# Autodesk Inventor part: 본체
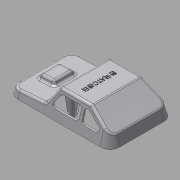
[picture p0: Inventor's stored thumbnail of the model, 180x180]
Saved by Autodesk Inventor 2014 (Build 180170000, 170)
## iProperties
Created: 2007-09
Part Number: 본체
Material: ABS 플라스틱
Document SubType Name: Modeling
Designer: Administrator
Density: 1.06 g/cm^3
Appearance: 매끄러움 - 흰색
Mass: 32.0135 g
Surface Area: 311.497 cm^2
Volume: 30.2014 cm^3
Author: Administrator
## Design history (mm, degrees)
sketch "스케치1"
  geometry: L1 (49, 38)-(-49, 38); L2 (-61, 26)-(-61, -26); L3 (-49, -38)-(49, -38); L4 (61, -26)-(61, 26); L5 (61, 38)-(-61, -38); L6 (-61, 38)-(61, -38); A1 r 12 centre (-49, 26) between (-49, 38) and (-61, 26); A2 r 12 centre (49, 26) between (61, 26) and (49, 38); A3 r 12 centre (49, -26) between (49, -38) and (61, -26); A4 r 12 centre (-49, -26) between (-61, -26) and (-49, -38); 1 further point
  constraints: 12 end point, 8 point on circle, 8 point on line, 8 tangent, 4 centre point, 3 equal radius, 2 midpoint, 2 parallel, 1 horizontal, 1 perpendicular
  dimensions: "d0" = 122 distance of L6.end L5.end; "d1" = 76 distance of L5.end L6.start; "d2" = 12 radius of A1
extrude "돌출1" new body sketch "스케치1" distance "d3" = 30; taper "d4" = -15 deg
sketch "스케치2"
  geometry: L1 (49, 30)-(-49, 30) reference; L2 (-49, 0)-(-61, 0) reference; L3 (-31, 30)-(-61, 30); L4 (-61, 30)-(-61, 10); L5 (-61, 10)-(-31, 30); 1 further point
  constraints: 6 end point, 1 collinear, 1 parallel, 1 perpendicular, 1 vertical alignment
  dimensions: "d6" = 20 distance of L3.end L4.end; "d7" = 30 distance of L3.start L3.end
extrude "돌출2" cut sketch "스케치2" stored distance "d8" = 10; taper "d9" = 0 deg
sketch "스케치3"
  geometry: L1 (61, 30)-(6.628, 30); L2 (6.628, 30)-(19, 10.201); L3 (19, 10.201)-(61, 8); L4 (61, 8)-(61, 30); L5 (49, 30)-(-31, 30) reference; L6 (61, 0)-(49, 0) reference; L7 (-49, 0)-(49, 0) reference; 1 further point
  constraints: 8 end point, 1 collinear, 1 horizontal, 1 perpendicular, 1 vertical alignment
  dimensions: "d10" = 8 distance of L6.start L3.end; "d11" = 3 deg angle of L7 L3; "d12" = 125 deg angle of L3 L2; "d13" = 42 horizontal distance of L2.end L6.start
extrude "돌출3" cut sketch "스케치3" stored distance "d14" = 10; taper "d15" = 0 deg
sketch "스케치4"
  geometry: L1 (-39.881, 9.267)-(-39.881, 61.267) reference; L2 (-31.476, 48.267)-(-11.476, 48.267); L3 (-11.476, 48.267)-(-11.476, 22.267); L4 (-11.476, 22.267)-(-31.476, 22.267); L5 (-31.476, 22.267)-(-31.476, 48.267); L6 (-42.476, 61.267)-(-42.476, 9.267) reference; 3 further points
  constraints: 8 end point, 2 midpoint, 2 parallel, 1 horizontal, 1 horizontal alignment, 1 perpendicular
  dimensions: "d16" = 20 distance between parallel lines of L5 L3; "d17" = 26 distance between parallel lines of L4 L2; "d82" = 11 distance between parallel lines of L5 L6
extrude "돌출4" join sketch "스케치4" distance "d19" = 5; taper "d20" = -20 deg
fillet "모깎기1" dims "d21" = 3
fillet "모깎기2" dims "d22" = 3
fillet "모깎기3" dims "d23" = 3
fillet "모깎기4" dims "d24" = 3
fillet "모깎기5" dims "d25" = 3
feature "쉘1" dims "d26" = 2
sketch "스케치7"
  geometry: L1 (18.172, 11.526)-(7.51, 28.59) reference; L2 (4.965, 30)-(-30.092, 30) reference; L3 (-31.756, 29.496)-(-50.664, 16.891) reference; L4 (10.362, 14.59)-(4.738, 23.59); L5 (2.194, 25)-(-17.77, 25); L6 (7.818, 10)-(-17.77, 10); L7 (-20.77, 13)-(-20.77, 22); L8 (-30.242, 24.496)-(-43.742, 15.496); L9 (-42.078, 10)-(-26.986, 10); L10 (-23.986, 13)-(-23.986, 22); L11 (-26.986, 25)-(-28.578, 25); A1 r 3 centre (-17.77, 13) between (-20.77, 13) and (-17.77, 10); A2 r 3 centre (-17.77, 22) between (-17.77, 25) and (-20.77, 22); A3 r 3 centre (2.194, 22) between (4.738, 23.59) and (2.194, 25); A4 r 3 centre (7.818, 13) between (7.818, 10) and (10.362, 14.59); A5 r 3 centre (-42.078, 13) between (-43.742, 15.496) and (-42.078, 10); A6 r 3 centre (-26.986, 13) between (-26.986, 10) and (-23.986, 13); A7 r 3 centre (-26.986, 22) between (-23.986, 22) and (-26.986, 25); A8 r 3 centre (-28.578, 22) between (-28.578, 25) and (-30.242, 24.496); 7 further points
  constraints: 16 end point, 16 point on circle, 16 tangent, 12 point on line, 8 centre point, 6 equal radius, 5 parallel, 3 perpendicular
  dimensions: "d27" = 5 distance between parallel lines of L2 L5; "d28" = 5 distance between parallel lines of L1 L4; "d29" = 34 distance of point (13.23, 10) point (-20.77, 10); "d30" = 15 distance of point (-20.77, 10) point (-20.77, 25); "d31" = 3 radius of A1; "d32" = 5 distance between parallel lines of L3 L8; "d33" = 5 distance between parallel lines of L2 L11; "d34" = 28 distance of point (-51.986, 10) point (-23.986, 10); "d35" = 15 distance of point (-23.986, 10) point (-23.986, 25); "d36" = 3 radius of A5
extrude "돌출5" cut sketch "스케치7" stored distance "d37" = 5; taper "d38" = 0 deg
sketch "스케치8"
  geometry: L1 (-49, 35.929)-(49, 35.929) reference; L2 (58.929, 26)-(58.929, -26) reference; L3 (49, -35.929)-(-49, -35.929) reference; L4 (-58.929, -26)-(-58.929, 26) reference; L5 (49, 36.929)-(-49, 36.929); L6 (-59.929, 26)-(-59.929, -26); L7 (-49, -36.929)-(49, -36.929); L8 (59.929, -26)-(59.929, 26); A1 r 9.929 centre (49, 26) between (58.929, 26) and (49, 35.929) reference; A2 r 9.929 centre (49, -26) between (49, -35.929) and (58.929, -26) reference; A3 r 9.929 centre (-49, -26) between (-58.929, -26) and (-49, -35.929) reference; A4 r 9.929 centre (-49, 26) between (-49, 35.929) and (-58.929, 26) reference; A5 r 10.929 centre (-49, 26) between (-49, 36.929) and (-59.929, 26); A6 r 10.929 centre (-49, -26) between (-59.929, -26) and (-49, -36.929); A7 r 10.929 centre (49, -26) between (49, -36.929) and (59.929, -26); A8 r 10.929 centre (49, 26) between (59.929, 26) and (49, 36.929); 1 further point
  constraints: 8 end point, 8 point on circle, 4 centre point, 7 other
  dimensions: "d39" = 1 distance between parallel lines of L5 L1
extrude "돌출6" join sketch "스케치8" distance "d40" = 1; taper "d41" = 0 deg
node "작업 평면1"
sketch "스케치9"
  geometry: A1 r 4 centre (21, 0) between (25, 0) and (17, 0); A2 r 4 centre (10, 0) between (14, 0) and (6, 0); A3 r 4 centre (-10, 0) between (-6, 0) and (-14, 0); A4 r 4 centre (-21, 0) between (-17, 0) and (-25, 0); 3 further points
  constraints: 8 point on circle, 4 centre point, 13 other
  dimensions: "d43" = 8 diameter of A1; "d44" = 8 diameter of A2; "d45" = 8 diameter of A3; "d46" = 8 diameter of A4; "d47" = 20 distance of A3.centre A2.centre; "d48" = 10 distance of point (0, 0) A2.centre; "d49" = 11 distance of A1.centre A2.centre; "d50" = 11 distance of A4.centre A3.centre
extrude "돌출7" join sketch "스케치9" stored distance "d51" = 1; taper "d52" = 0 deg
sketch "스케치13"
  geometry: C1 r 3 at (-40, 0); C2 r 3 at (40, 0); C3 r 3 at (0, -22); C4 r 3 at (0, 22); 1 further point
  constraints: 4 centre point, 2 horizontal alignment, 2 vertical alignment
  dimensions: "d83" = 6 diameter of C1; "d84" = 6 diameter of C2; "d85" = 6 diameter of C3; "d86" = 6 diameter of C4; "d87" = 44 distance of C3.centre C4.centre; "d88" = 22 distance of C3.centre point (0, 0); "d89" = 40 distance of C1.centre point (0, 0); "d90" = 40 distance of C2.centre point (0, 0)
extrude "돌출10" join sketch "스케치13" stored distance "d91" = 1; taper "d92" = 2 deg
node "작업 평면3"
sketch "스케치14"
  geometry: L1 (-45, 1)-(-35, 1); L2 (-35, 1)-(-35, -1); L3 (-35, -1)-(-45, -1); L4 (-45, -1)-(-45, 1); L5 (-45, 1)-(-35, -1); L6 (-35, 1)-(-45, -1); L7 (5, 23)-(-5, 23); L8 (-5, 23)-(-5, 21); L9 (-5, 21)-(5, 21); L10 (5, 21)-(5, 23); L11 (5, 23)-(-5, 21); L12 (-5, 23)-(5, 21); L13 (35, 1)-(45, 1); L14 (45, 1)-(45, -1); L15 (45, -1)-(35, -1); L16 (35, -1)-(35, 1); L17 (35, 1)-(45, -1); L18 (45, 1)-(35, -1); L19 (5, -21)-(-5, -21); L20 (-5, -21)-(-5, -23); L21 (-5, -23)-(5, -23); L22 (5, -23)-(5, -21); L23 (5, -21)-(-5, -23); L24 (-5, -21)-(5, -23); C1 r 3 at (0, -22) reference; C2 r 3 at (0, 22) reference; C3 r 3 at (40, 0) reference; C4 r 3 at (-40, 0) reference; 1 further point
  constraints: 48 end point, 8 midpoint, 8 parallel, 4 horizontal, 4 perpendicular
  dimensions: "d94" = 10 distance of L2.end L3.end; "d95" = 2 distance of L1.end L2.end; "d96" = 10 distance of L9.end L8.end; "d97" = 2 distance of L8.end L7.end; "d98" = 10 distance of L14.end L15.end; "d99" = 2 distance of L13.end L14.end; "d100" = 10 distance of L21.end L20.end; "d101" = 2 distance of L20.end L19.end
extrude "돌출11" join sketch "스케치14" stored distance "d102" = 1; taper "d103" = 0.5 deg
sketch "스케치15"
  geometry: L1 (2.098, 0)-(2.324, -26.001) reference; L2 (2.098, 0)-(6.682, -26.001); L3 (27.189, -27.941)-(-7.868, -27.941) reference; L4 (2.324, -26.001)-(6.682, -26.001); 1 further point
  constraints: 4 end point, 1 parallel
  dimensions: "d104" = 80 deg angle of L3 L2
extrude "돌출12" join sketch "스케치15" stored distance "d105" = 1; taper "d106" = 0 deg
sketch "스케치16"
  geometry: L1 (0, 0)-(-3.68, -20.872); L2 (35.092, -27.941)-(0.035, -27.941) reference; L3 (-0.813, -25.471)-(-11.476, -8.367) reference; L4 (-3.68, -20.872)-(0.035, -27.941); L5 (0.035, -27.941)-(0, 0); 1 further point
  constraints: 6 end point, 1 point on line
  dimensions: "d107" = 100 deg angle of L2 L1
extrude "돌출13" join sketch "스케치16" stored distance "d108" = 1; taper "d109" = 0 deg
sketch "스케치17"
  geometry: L1 (0, 0)-(-0.201, -23.065) reference; L2 (0, 0)-(-4.89, -27.73); L3 (-4.908, -27.749)-(-39.965, -27.749) reference; L4 (-4.908, -27.749)-(-0.201, -23.065); L5 (0, 0)-(-0.201, -23.065); 1 further point
  constraints: 6 end point, 1 collinear, 1 point on line
  dimensions: "d110" = 100 deg angle of L3 L2
extrude "돌출14" join sketch "스케치17" stored distance "d111" = 1; taper "d112" = 0 deg
sketch "스케치18"
  geometry: L1 (-12.811, -27.749)-(-47.868, -27.749) reference; L2 (2.098, 0)-(4.62, -14.304); L3 (6.652, -12.946)-(-12.256, -25.581) reference; L4 (2.098, 0)-(2.239, -16.17); L5 (2.239, -16.17)-(4.62, -14.304); 1 further point
  constraints: 6 end point, 1 point on line
  dimensions: "d113" = 100 deg angle of L2 L1
extrude "돌출15" join sketch "스케치18" stored distance "d114" = 1; taper "d115" = 0 deg
sketch "스케치19"
  geometry: L1 (1.761, -9.935)-(-0.086, -9.839) reference; L2 (0, 0)-(-0.086, -9.839) reference; L3 (0, 0)-(-1.72, -9.753); L4 (75.092, -27.749)-(40.035, -27.749) reference; L5 (10.467, -10.303)-(-1.675, -9.667) reference; L6 (0, 0)-(-0.086, -9.839); L7 (10.363, -12.3)-(-1.78, -11.664) reference; L8 (-1.676, -9.668)-(10.466, -10.304) reference; L9 (-1.72, -9.753)-(-0.086, -9.839); 3 further points; 2 other entities
  constraints: 6 end point, 1 point on line, 2 other
  dimensions: "d116" = 100 deg angle of L4 L3
extrude "돌출16" join sketch "스케치19" stored distance "d117" = 1; taper "d118" = 0 deg
sketch "스케치20"
  geometry: L1 (2.098, 0)-(2.188, -10.372) reference; L2 (2.098, 0)-(3.728, -9.246); L3 (67.189, -27.749)-(32.132, -27.749) reference; L4 (2.46, -12.3)-(-9.682, -11.664) reference; L5 (-9.579, -9.668)-(2.564, -10.304) reference; L6 (3.975, -8.661)-(3.538, -9.695) reference; L7 (2.098, 0)-(2.188, -10.372); L8 (3.943, -10.464)-(2.188, -10.372); L9 (3.728, -9.246)-(3.943, -10.464); 5 further points; 3 other entities
  constraints: 8 end point, 2 collinear, 1 point on line, 4 other
  dimensions: "d119" = 100 deg angle of L3 L2
extrude "돌출17" join sketch "스케치20" stored distance "d120" = 1; taper "d121" = 0 deg
sketch "스케치21"
  geometry: C1 r 3 at (0, 0) reference; C2 r 3 at (-40, -22) reference; C3 r 3 at (0, -44) reference; C4 r 3 at (40, -22) reference; 5 further points
  constraints: 4 coincident
hole "구멍1" sketch "스케치21" at (0, 0), (-40, -22), (0, -44), (40, -22) diameter "d122" = 3.242; stored, may be unused: countersink angle "d126" = 90 deg, drill point angle "d128" = 118 deg; dims "d123" = 9, "d124" = 4, "d125" = 2, "d127" = 11
sketch "스케치22"
  geometry: L1 (61, -26)-(61, 26) reference; 2 further points
  constraints: 1 horizontal alignment, 1 other
  dimensions: "d129" = 50 distance from line of point (11, 0) L1
feature "엠보싱1" sketch "스케치22" dims "d0" = 122, "d1" = 76, "d2" = 12, "d130" = 0.5, "d131" = 0
chamfer "모따기1" distance "d132" = 1; stored, may be unused: second distance "d133" = 2, angle "d134" = 45 deg
node "솔리드1"
mirror "대칭1"
node "투영된 루프4"
node "투영된 루프5"
node "투영된 루프6"
node "투영된 루프7"
node "투영된 루프8"
node "투영된 루프9"
node "투영된 루프10"
node "투영된 루프11"
node "투영된 루프12"
other parameters: "d42" = -63, "d93" = 2
